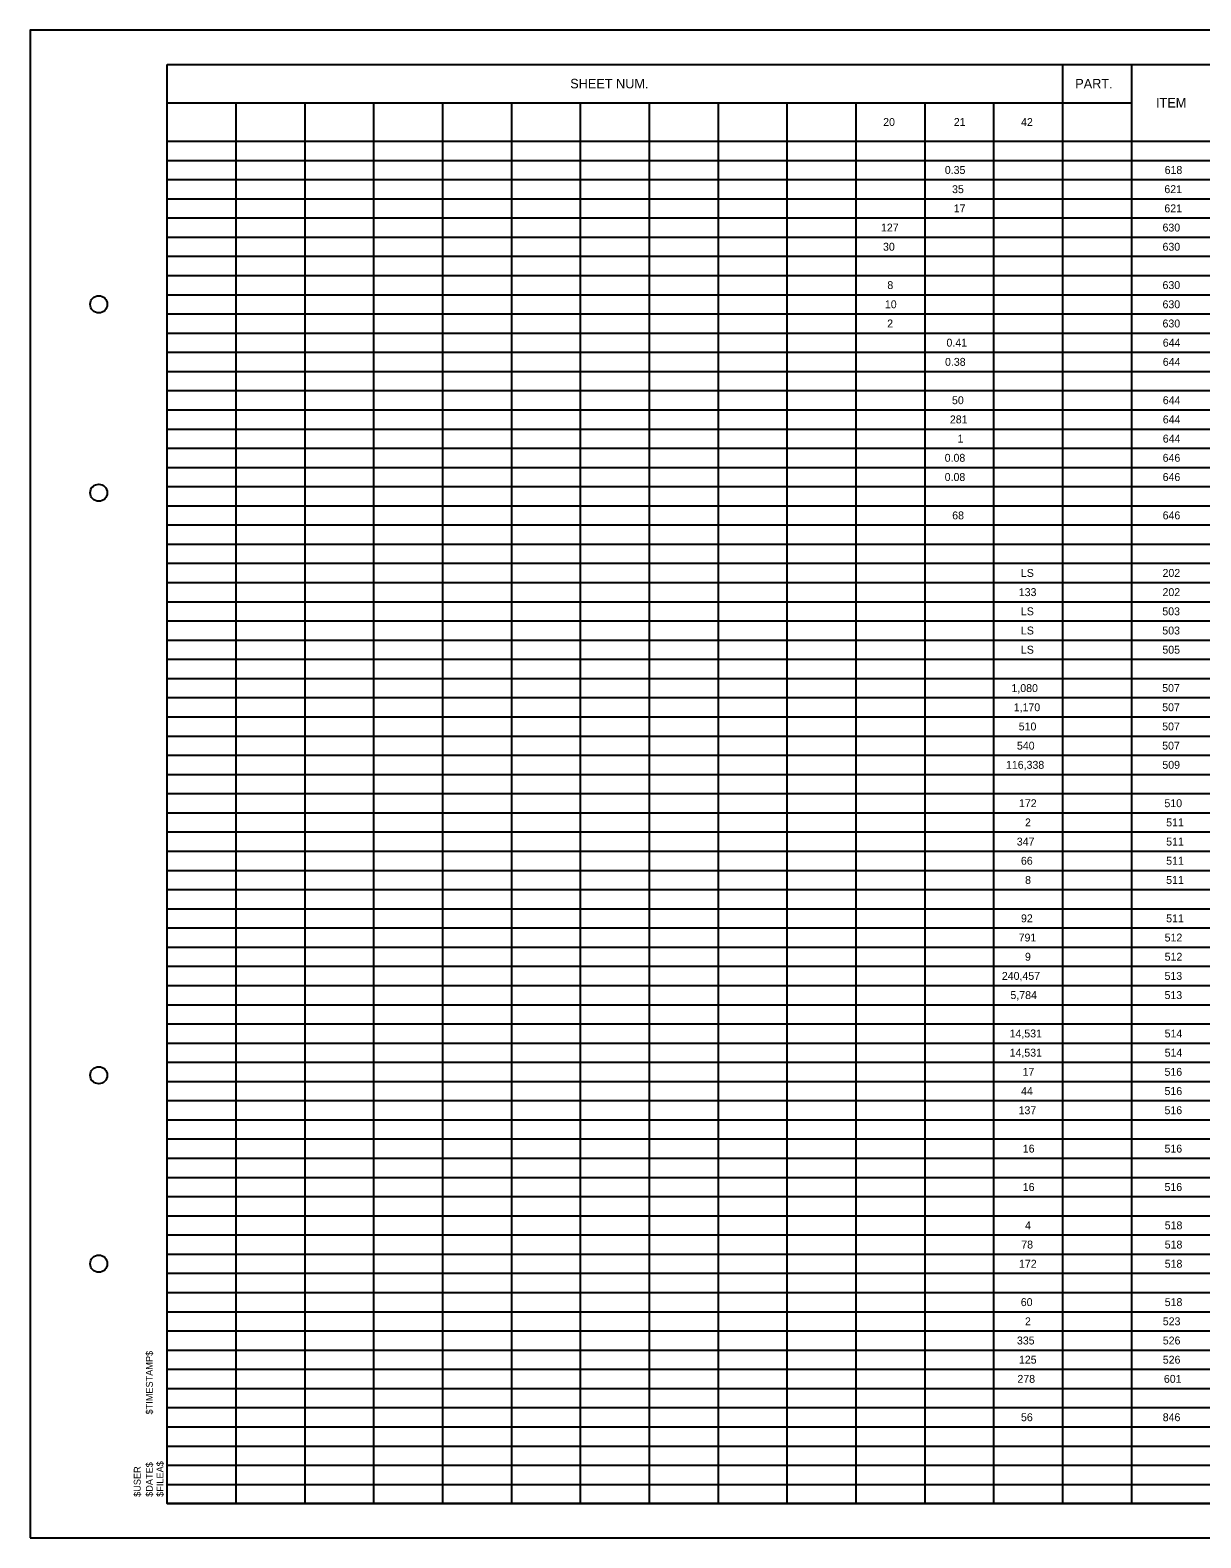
# Model space of a CAD drawing. Extents: x 0 to 34, y 0 to 22.
# Drawn here: x 0 to 17.07, y 0 to 22 of the extents above; entities that cross this region are included whole.
import ezdxf

# ---------------------------------------------------------------- set-up
doc = ezdxf.new("R2010")
doc.units = 0
for name, color, linetype in [('SH_Border', 7, 'Continuous'), ('SH_Cut_Line', 7, 'Continuous'), ('SH_Data', 7, 'Continuous'), ('SH_Text', 7, 'Continuous')]:
    doc.layers.add(name, color=color, linetype=linetype)

msp = doc.modelspace()

# ---------------------------------------------------------------- linework, layer by layer
at = {"layer": 'SH_Border'}
msp.add_lwpolyline([(2, 21.5), (33.5, 21.5), (33.5, 0.5), (2, 0.5)], close=True, dxfattribs=at)
for centre in [(1, 18), (1, 15.25), (1, 6.75), (1, 4)]:
    msp.add_circle(centre, 0.125, dxfattribs=at)
at = {"layer": 'SH_Cut_Line'}
msp.add_lwpolyline([(0, 0), (34, 0), (34, 22), (0, 22)], close=True, dxfattribs=at)
at = {"layer": 'SH_Text'}
for p, q in [((2, 21.5), (2, 21.5)), ((2, 21.5), (32.5, 21.5)), ((2, 0.5), (2, 21.5)), ((15.06, 0.5), (15.06, 21.5)), ((16.064, 0.5), (16.064, 21.5)), ((2, 20.94), (16.064, 20.94)), ((3.005, 0.5), (3.005, 20.94)), ((4.009, 0.5), (4.009, 20.94)), ((5.014, 0.5), (5.014, 20.94)), ((6.018, 0.5), (6.018, 20.94)), ((7.023, 0.5), (7.023, 20.94)), ((8.028, 0.5), (8.028, 20.94)), ((9.032, 0.5), (9.032, 20.94)), ((10.037, 0.5), (10.037, 20.94)), ((11.041, 0.5), (11.041, 20.94)), ((12.046, 0.5), (12.046, 20.94)), ((13.05, 0.5), (13.05, 20.94)), ((14.055, 0.5), (14.055, 20.94)), ((2, 20.38), (15.06, 20.38)), ((14.055, 20.38), (32.5, 20.38)), ((2, 20.1), (32.5, 20.1)), ((2, 19.82), (32.5, 19.82)), ((2, 19.54), (32.5, 19.54)), ((2, 19.26), (32.5, 19.26)), ((2, 18.98), (32.5, 18.98)), ((2, 18.7), (32.5, 18.7)), ((2, 18.42), (32.5, 18.42)), ((2, 18.14), (32.5, 18.14)), ((2, 17.86), (32.5, 17.86)), ((2, 17.58), (32.5, 17.58)), ((2, 17.3), (32.5, 17.3)), ((2, 17.02), (32.5, 17.02)), ((2, 16.74), (32.5, 16.74)), ((2, 16.46), (32.5, 16.46)), ((2, 16.18), (32.5, 16.18)), ((2, 15.9), (32.5, 15.9)), ((2, 15.62), (32.5, 15.62)), ((2, 15.34), (32.5, 15.34)), ((2, 15.06), (32.5, 15.06)), ((2, 14.78), (32.5, 14.78)), ((2, 14.5), (32.5, 14.5)), ((2, 14.22), (32.5, 14.22)), ((2, 13.94), (32.5, 13.94)), ((2, 13.66), (32.5, 13.66)), ((2, 13.38), (32.5, 13.38)), ((2, 13.1), (32.5, 13.1)), ((2, 12.82), (32.5, 12.82)), ((2, 12.54), (32.5, 12.54)), ((2, 12.26), (32.5, 12.26)), ((2, 11.98), (32.5, 11.98)), ((2, 11.7), (32.5, 11.7)), ((2, 11.42), (32.5, 11.42)), ((2, 11.14), (32.5, 11.14)), ((2, 10.86), (32.5, 10.86)), ((2, 10.58), (32.5, 10.58)), ((2, 10.3), (32.5, 10.3)), ((2, 10.02), (32.5, 10.02)), ((2, 9.74), (32.5, 9.74)), ((2, 9.46), (32.5, 9.46)), ((2, 9.18), (32.5, 9.18)), ((2, 8.9), (32.5, 8.9)), ((2, 8.62), (32.5, 8.62)), ((2, 8.34), (32.5, 8.34)), ((2, 8.06), (32.5, 8.06)), ((2, 7.78), (32.5, 7.78)), ((2, 7.5), (32.5, 7.5)), ((2, 7.22), (32.5, 7.22)), ((2, 6.94), (32.5, 6.94)), ((2, 6.66), (32.5, 6.66)), ((2, 6.38), (32.5, 6.38)), ((2, 6.1), (32.5, 6.1)), ((2, 5.82), (32.5, 5.82)), ((2, 5.54), (32.5, 5.54)), ((2, 5.26), (32.5, 5.26)), ((2, 4.98), (32.5, 4.98)), ((2, 4.7), (32.5, 4.7)), ((2, 4.42), (32.5, 4.42)), ((2, 4.14), (32.5, 4.14)), ((2, 3.86), (32.5, 3.86)), ((2, 3.58), (32.5, 3.58)), ((2, 3.3), (32.5, 3.3)), ((2, 3.02), (32.5, 3.02)), ((2, 2.74), (32.5, 2.74)), ((2, 2.46), (32.5, 2.46)), ((2, 2.18), (32.5, 2.18)), ((2, 1.9), (32.5, 1.9)), ((2, 1.62), (32.5, 1.62)), ((2, 1.34), (32.5, 1.34)), ((2, 1.06), (32.5, 1.06)), ((2, 0.78), (32.5, 0.78)), ((2, 0.5), (32.5, 0.5))]:
    msp.add_line(p, q, dxfattribs=at)

# ---------------------------------------------------------------- texts
at = {"layer": 'SH_Data'}
for s, p in [('$TIMESTAMP$', (1.788, 1.8)), ('$DATE$', (1.788, 0.598)), ('$FILEA$', (1.944, 0.598)), ('$USER', (1.611, 0.598))]:
    msp.add_text(s, height=0.1, rotation=89.9931, dxfattribs=at).set_placement(p)
at = {"layer": 'SH_Text'}
for s, height, p in [('SHEET NUM.', 0.1384, (7.876, 21.151)), ('PART.', 0.1384, (15.241, 21.151)), ('ITEM', 0.1384, (16.419, 20.871)), ('20', 0.1153, (12.44, 20.602)), ('21', 0.1153, (13.47, 20.602)), ('42', 0.1153, (14.451, 20.602)), ('0.35', 0.1153, (13.339, 19.902)), ('618', 0.1153, (16.545, 19.902)), ('35', 0.1153, (13.445, 19.622)), ('621', 0.1153, (16.541, 19.622)), ('17', 0.1153, (13.469, 19.342)), ('621', 0.1153, (16.541, 19.342)), ('127', 0.1153, (12.408, 19.062)), ('630', 0.1153, (16.514, 19.062)), ('30', 0.1153, (12.438, 18.782)), ('630', 0.1153, (16.514, 18.782)), ('8', 0.115, (12.501, 18.222)), ('630', 0.1153, (16.514, 18.222)), ('10', 0.1153, (12.465, 17.942)), ('630', 0.1153, (16.514, 17.942)), ('2', 0.115, (12.499, 17.662)), ('630', 0.1153, (16.514, 17.662)), ('0.41', 0.1153, (13.363, 17.382)), ('644', 0.1153, (16.518, 17.382)), ('0.38', 0.1153, (13.342, 17.102)), ('644', 0.1153, (16.518, 17.102)), ('50', 0.1153, (13.444, 16.542)), ('644', 0.1153, (16.518, 16.542)), ('281', 0.1153, (13.413, 16.262)), ('644', 0.1153, (16.518, 16.262)), ('1', 0.115, (13.525, 15.982)), ('644', 0.1153, (16.518, 15.982)), ('0.08', 0.1153, (13.337, 15.702)), ('646', 0.1153, (16.516, 15.702)), ('0.08', 0.1153, (13.337, 15.422)), ('646', 0.1153, (16.516, 15.422)), ('68', 0.1153, (13.447, 14.862)), ('646', 0.1153, (16.516, 14.862)), ('LS', 0.1153, (14.449, 14.022)), ('202', 0.1153, (16.514, 14.022)), ('133', 0.1153, (14.418, 13.742)), ('202', 0.1153, (16.514, 13.742)), ('LS', 0.1153, (14.449, 13.462)), ('503', 0.1153, (16.511, 13.462)), ('LS', 0.1153, (14.449, 13.182)), ('503', 0.1153, (16.511, 13.182)), ('LS', 0.1153, (14.449, 12.902)), ('505', 0.1153, (16.512, 12.902)), ('1,080', 0.1153, (14.311, 12.342)), ('507', 0.1153, (16.509, 12.342)), ('1,170', 0.1153, (14.344, 12.062)), ('507', 0.1153, (16.509, 12.062)), ('510', 0.1153, (14.417, 11.782)), ('507', 0.1153, (16.509, 11.782)), ('540', 0.1153, (14.391, 11.502)), ('507', 0.1153, (16.509, 11.502)), ('116,338', 0.1153, (14.231, 11.222)), ('509', 0.1153, (16.512, 11.222)), ('172', 0.1153, (14.421, 10.662)), ('510', 0.1153, (16.542, 10.662)), ('2', 0.115, (14.508, 10.382)), ('511', 0.1153, (16.567, 10.382)), ('347', 0.1153, (14.389, 10.102)), ('511', 0.1153, (16.567, 10.102)), ('66', 0.1153, (14.449, 9.822)), ('511', 0.1153, (16.567, 9.822)), ('8', 0.115, (14.51, 9.542)), ('511', 0.1153, (16.567, 9.542)), ('92', 0.1153, (14.45, 8.982)), ('511', 0.1153, (16.567, 8.982)), ('791', 0.1153, (14.416, 8.702)), ('512', 0.1153, (16.545, 8.702)), ('9', 0.115, (14.508, 8.422)), ('512', 0.1153, (16.545, 8.422)), ('240,457', 0.1153, (14.171, 8.142)), ('513', 0.1153, (16.543, 8.142)), ('5,784', 0.1153, (14.296, 7.862)), ('513', 0.1153, (16.543, 7.862)), ('14,531', 0.1153, (14.284, 7.302)), ('514', 0.1153, (16.545, 7.302)), ('14,531', 0.1153, (14.284, 7.022)), ('514', 0.1153, (16.545, 7.022)), ('17', 0.1153, (14.473, 6.742)), ('516', 0.1153, (16.543, 6.742)), ('44', 0.1153, (14.451, 6.462)), ('516', 0.1153, (16.543, 6.462)), ('137', 0.1153, (14.415, 6.182)), ('516', 0.1153, (16.543, 6.182)), ('16', 0.1153, (14.476, 5.622)), ('516', 0.1153, (16.543, 5.622)), ('16', 0.1153, (14.476, 5.062)), ('516', 0.1153, (16.543, 5.062)), ('4', 0.115, (14.509, 4.502)), ('518', 0.1153, (16.546, 4.502)), ('78', 0.1153, (14.454, 4.222)), ('518', 0.1153, (16.546, 4.222)), ('172', 0.1153, (14.421, 3.942)), ('518', 0.1153, (16.546, 3.942)), ('60', 0.1153, (14.447, 3.382)), ('518', 0.1153, (16.546, 3.382)), ('2', 0.115, (14.508, 3.102)), ('523', 0.1153, (16.518, 3.102)), ('335', 0.1153, (14.391, 2.822)), ('526', 0.1153, (16.518, 2.822)), ('125', 0.1153, (14.42, 2.542)), ('526', 0.1153, (16.518, 2.542)), ('278', 0.1153, (14.398, 2.262)), ('601', 0.1153, (16.534, 2.262)), ('56', 0.1153, (14.45, 1.702)), ('846', 0.1153, (16.517, 1.702))]:
    msp.add_text(s, height=height, dxfattribs=at).set_placement(p)

doc.saveas('drawing.dxf')
